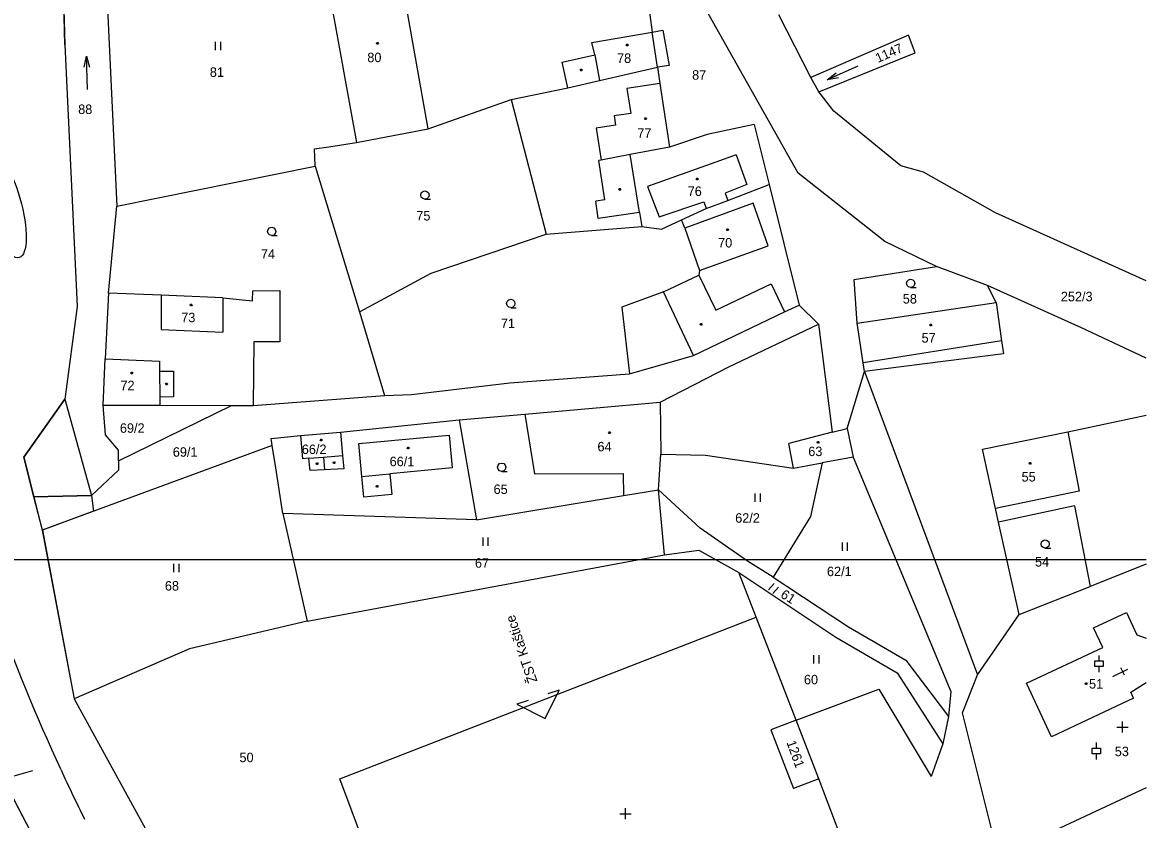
# Model space of a CAD drawing. Extents: x -812394 to -807601, y -1013097 to -1009266.
# Drawn here: x -809827.1 to -809625.5, y -1011046.5 to -1010903.7 of the extents above; entities that cross this region are included whole.
import ezdxf

# ---------------------------------------------------------------- set-up
doc = ezdxf.new("R2010")
doc.units = 0
for name, color, linetype in [('Default', 7, 'Continuous'), ('dočasné zábory', 7, 'Continuous'), ('KLADY_ZMVM', 7, 'Continuous'), ('KN_HRANICE', 7, 'Continuous'), ('KN_KULTURY', 7, 'Continuous'), ('KN_PARCELY', 7, 'Continuous'), ('KN_SLUCKY', 7, 'Continuous'), ('obvod_stavby', 7, 'Continuous'), ('SO02 - Železniční svršek', 7, 'Continuous'), ('SO_Bubliny', 7, 'Continuous')]:
    doc.layers.add(name, color=color, linetype=linetype)

# ---------------------------------------------------------------- blocks, each defined once
blk = doc.blocks.new('304')
at = {"layer": 'Default'}
blk.add_lwpolyline([(0, 0), (-0.38, 0.1), (-0.65, 0.37), (-0.75, 0.74), (-0.65, 1.11), (-0.38, 1.38), (-0.01, 1.48), (0.36, 1.38), (0.63, 1.11), (0.73, 0.73), (0.63, 0.35), (0.36, 0.08), (-0.02, -0.02), (0.98, -0.02)], dxfattribs=at)
blk = doc.blocks.new('306')
at = {"layer": 'Default'}
for p, q in [((-0.5, 1.5), (-0.5, 0)), ((0.5, 0), (0.5, 1.5))]:
    blk.add_line(p, q, dxfattribs=at)
blk = doc.blocks.new('315')
at = {"layer": 'Default'}
for p, q in [((-1, 1), (1, 1)), ((0, 0), (0, 2))]:
    blk.add_line(p, q, dxfattribs=at)
blk = doc.blocks.new('NAHRADNI_SYMBOL')
at = {"layer": 'Default'}
blk.add_lwpolyline([(0.09, 0.15), (0.18, 0), (0.09, -0.15), (-0.09, -0.15), (-0.18, 0), (-0.09, 0.15), (0.09, 0.15)], dxfattribs=at)
blk = doc.blocks.new('802')
at = {"layer": 'Default'}
blk.add_line((-3, 0), (3, 0), dxfattribs=at)
blk.add_lwpolyline([(1, 0.5), (3, 0), (1, -0.5)], dxfattribs=at)
blk = doc.blocks.new('318')
at = {"layer": 'Default'}
blk.add_line((0, 2), (0, 3), dxfattribs=at)
blk.add_lwpolyline([(0, 0), (0, 1), (-0.75, 1), (-0.75, 2), (0, 2), (0.75, 2), (0.75, 1), (0, 1)], dxfattribs=at)
blk = doc.blocks.new('402')
at = {"layer": 'Default'}
blk.add_lwpolyline([(0.09, 0.15), (0.18, 0), (0.09, -0.15), (-0.09, -0.15), (-0.18, 0), (-0.09, 0.15), (0.09, 0.15)], dxfattribs=at)
blk = doc.blocks.new('4091')
at = {"layer": 'Default'}
for p, q in [((0, 0), (0, 3)), ((0.75, 2), (-0.75, 2))]:
    blk.add_line(p, q, dxfattribs=at)

msp = doc.modelspace()

# ---------------------------------------------------------------- linework, layer by layer
at = {"layer": 'Default'}
msp.add_lwpolyline([(-809736.51, -1011025.2), (-809738.53, -1011025.87), (-809733.47, -1011028.41), (-809730.93, -1011023.35), (-809732.95, -1011024.02)], dxfattribs=at)
at = {"layer": 'dočasné zábory'}
msp.add_lwpolyline([(-809825.08, -1010988.69), (-809826.87, -1010981.55), (-809819.55, -1010971.16), (-809814.76, -1010988.43)], close=True, dxfattribs=at)
msp.add_lwpolyline([(-809823.56, -1010994.65), (-809825.08, -1010988.69), (-809814.76, -1010988.43), (-809814.4, -1010991.28), (-809823.56, -1010994.65)], dxfattribs=at)
at = {"layer": 'KLADY_ZMVM'}
msp.add_lwpolyline([(-809625.71, -1011000), (-810000, -1011000), (-810000, -1011500), (-809375, -1011500), (-809375, -1011000)], dxfattribs=at)
at = {"layer": 'KN_HRANICE'}
for p, q in [((-809820.27, -1010877.38), (-809819.54, -1010907.65)), ((-809754.39, -1010922.74), (-809759.51, -1010893.83)), ((-809772.62, -1010895.72), (-809767.28, -1010925.14)), ((-809715.33, -1010897.38), (-809714.24, -1010905.37)), ((-809688.11, -1010930.67), (-809707.45, -1010896.24)), ((-809811.97, -1010899.94), (-809810.23, -1010936.6)), ((-809685.82, -1010913.52), (-809691.58, -1010902.27)), ((-809725.07, -1010907.24), (-809714.24, -1010905.37)), ((-809714.24, -1010905.37), (-809712.36, -1010905.04)), ((-809712.36, -1010905.04), (-809711.25, -1010911.34)), ((-809819.54, -1010907.65), (-809817.34, -1010954.54)), ((-809724.57, -1010909.43), (-809725.07, -1010907.24)), ((-809730.42, -1010910.76), (-809724.57, -1010909.43)), ((-809729.38, -1010915.34), (-809730.42, -1010910.76)), ((-809723.69, -1010914.05), (-809713.3, -1010911.69)), ((-809711.25, -1010911.34), (-809713.3, -1010911.69)), ((-809713.3, -1010911.69), (-809712.87, -1010914.61)), ((-809684.42, -1010916.06), (-809685.82, -1010913.52)), ((-809739.53, -1010917.47), (-809729.38, -1010915.34)), ((-809729.38, -1010915.34), (-809723.69, -1010914.05)), ((-809712.87, -1010914.61), (-809711.14, -1010925.98)), ((-809754.39, -1010922.74), (-809739.53, -1010917.47)), ((-809739.53, -1010917.47), (-809733.26, -1010941.62)), ((-809681.71, -1010919.57), (-809684.42, -1010916.06)), ((-809669.73, -1010929.35), (-809681.71, -1010919.57)), ((-809767.28, -1010925.14), (-809754.39, -1010922.74)), ((-809704.43, -1010923.75), (-809711.14, -1010925.98)), ((-809695.97, -1010921.93), (-809704.43, -1010923.75)), ((-809695.97, -1010921.93), (-809693.3, -1010932.7)), ((-809772.22, -1010925.97), (-809767.28, -1010925.14)), ((-809774.81, -1010926.31), (-809772.22, -1010925.97)), ((-809774.68, -1010929.4), (-809774.81, -1010926.31)), ((-809711.14, -1010925.98), (-809718.2, -1010927.32)), ((-809716.52, -1010937.73), (-809718.2, -1010927.32)), ((-809810.23, -1010936.6), (-809774.68, -1010929.4)), ((-809774.68, -1010929.4), (-809766.75, -1010955.54)), ((-809665.64, -1010930.47), (-809669.73, -1010929.35)), ((-809672.58, -1010942.91), (-809688.11, -1010930.67)), ((-809652.76, -1010937.76), (-809665.64, -1010930.47)), ((-809700.73, -1010935.54), (-809693.3, -1010932.7)), ((-809693.3, -1010932.7), (-809687.95, -1010954.31)), ((-809704.57, -1010937), (-809700.73, -1010935.54)), ((-809811.73, -1010952.15), (-809810.23, -1010936.6)), ((-809716.52, -1010937.73), (-809716.12, -1010940.23)), ((-809708.99, -1010939.05), (-809704.57, -1010937)), ((-809625.71, -1010949.98), (-809652.76, -1010937.76)), ((-809712.62, -1010940.73), (-809708.99, -1010939.05)), ((-809708.43, -1010940.5), (-809708.99, -1010939.05)), ((-809753.89, -1010948.61), (-809733.26, -1010941.62)), ((-809733.26, -1010941.62), (-809716.12, -1010940.23)), ((-809716.12, -1010940.23), (-809712.62, -1010940.73)), ((-809708.43, -1010940.5), (-809705.79, -1010948.11)), ((-809663.31, -1010947.39), (-809672.58, -1010942.91)), ((-809678.08, -1010949.7), (-809663.31, -1010947.39)), ((-809654.15, -1010950.78), (-809663.31, -1010947.39)), ((-809766.75, -1010955.54), (-809753.89, -1010948.61)), ((-809712.21, -1010951.96), (-809705.9, -1010948.93)), ((-809705.79, -1010948.11), (-809705.9, -1010948.93)), ((-809677.51, -1010957.55), (-809678.08, -1010949.7)), ((-809785.87, -1010953.57), (-809785.81, -1010951.78)), ((-809785.81, -1010951.78), (-809780.99, -1010951.72)), ((-809780.99, -1010951.72), (-809780.99, -1010960.93)), ((-809712.21, -1010951.96), (-809719.69, -1010954.69)), ((-809637.34, -1010958.4), (-809654.15, -1010950.78)), ((-809652.62, -1010953.83), (-809654.15, -1010950.78)), ((-809811.73, -1010952.15), (-809812.29, -1010963.93)), ((-809802.28, -1010952.55), (-809811.73, -1010952.15)), ((-809791.19, -1010953.02), (-809802.28, -1010952.55)), ((-809802.28, -1010952.55), (-809802.28, -1010958.7)), ((-809791.19, -1010953.02), (-809785.87, -1010953.57)), ((-809791.19, -1010953.02), (-809791.19, -1010959.17)), ((-809677.51, -1010957.55), (-809652.62, -1010953.83)), ((-809652.62, -1010953.83), (-809651.63, -1010960.74)), ((-809817.34, -1010954.54), (-809819.55, -1010971.19)), ((-809766.75, -1010955.54), (-809762.22, -1010970.5)), ((-809719.69, -1010954.69), (-809718.32, -1010966.65)), ((-809706.83, -1010963.33), (-809690.53, -1010955.54)), ((-809690.53, -1010955.54), (-809687.95, -1010954.31)), ((-809687.95, -1010954.31), (-809684.45, -1010957.75)), ((-809700.5, -1010965.4), (-809684.45, -1010957.75)), ((-809684.45, -1010957.75), (-809682.01, -1010977.11)), ((-809676.47, -1010964.65), (-809677.51, -1010957.55)), ((-809802.28, -1010958.7), (-809791.19, -1010959.17)), ((-809625.71, -1010963.85), (-809637.34, -1010958.4)), ((-809785.63, -1010960.93), (-809785.75, -1010972.3)), ((-809780.99, -1010960.93), (-809785.63, -1010960.93)), ((-809651.63, -1010960.74), (-809651.3, -1010963.06)), ((-809812.69, -1010972.27), (-809812.29, -1010963.93)), ((-809718.32, -1010966.65), (-809706.83, -1010963.33)), ((-809651.3, -1010963.06), (-809676.23, -1010966.23)), ((-809712.82, -1010971.72), (-809700.5, -1010965.4)), ((-809676.23, -1010966.23), (-809676.47, -1010964.65)), ((-809739.76, -1010968.28), (-809718.32, -1010966.65)), ((-809679.34, -1010976.42), (-809676.23, -1010966.23)), ((-809676.23, -1010966.23), (-809655.96, -1011020.63)), ((-809757.42, -1010970.37), (-809739.76, -1010968.28)), ((-809819.55, -1010971.19), (-809826.87, -1010981.55)), ((-809785.75, -1010972.3), (-809762.22, -1010970.5)), ((-809762.22, -1010970.5), (-809757.42, -1010970.37)), ((-809737.1, -1010973.85), (-809712.82, -1010971.72)), ((-809712.82, -1010971.72), (-809712.69, -1010981.07)), ((-809812.22, -1010977.58), (-809812.69, -1010972.27)), ((-809812.69, -1010972.27), (-809802.49, -1010972.27)), ((-809809.94, -1010982.24), (-809789.65, -1010972.3)), ((-809802.49, -1010972.27), (-809789.65, -1010972.3)), ((-809789.65, -1010972.3), (-809785.75, -1010972.3)), ((-809748.85, -1010974.88), (-809737.1, -1010973.85)), ((-809737.1, -1010973.85), (-809735.37, -1010984.59)), ((-809639.78, -1010977.02), (-809625.71, -1010974.08)), ((-809770.14, -1010977.1), (-809748.85, -1010974.88)), ((-809748.85, -1010974.88), (-809745.78, -1010992.82)), ((-809809.94, -1010980.34), (-809812.22, -1010977.58)), ((-809782.57, -1010978.23), (-809777.31, -1010977.72)), ((-809777.31, -1010977.72), (-809770.14, -1010977.1)), ((-809777.31, -1010977.72), (-809776.92, -1010981.88)), ((-809770.14, -1010977.1), (-809769.76, -1010981.28)), ((-809682.01, -1010977.11), (-809679.34, -1010976.42)), ((-809679.34, -1010976.42), (-809678.26, -1010981.58)), ((-809655.06, -1010980.16), (-809639.78, -1010977.02)), ((-809782.36, -1010979.51), (-809823.59, -1010994.66)), ((-809782.36, -1010979.51), (-809782.57, -1010978.23)), ((-809781.71, -1010983.51), (-809782.36, -1010979.51)), ((-809652.76, -1010990.81), (-809655.06, -1010980.16)), ((-809826.87, -1010981.55), (-809825.08, -1010988.69)), ((-809809.94, -1010982.24), (-809809.94, -1010980.34)), ((-809809.94, -1010982.24), (-809809.94, -1010983.94)), ((-809775.78, -1010981.78), (-809776.92, -1010981.88)), ((-809775.61, -1010983.58), (-809775.78, -1010981.78)), ((-809769.76, -1010981.28), (-809769.54, -1010983.67)), ((-809713.13, -1010987.41), (-809712.69, -1010981.07)), ((-809712.69, -1010981.07), (-809704.69, -1010981.22)), ((-809704.69, -1010981.22), (-809688.94, -1010983.58)), ((-809678.26, -1010981.58), (-809683.77, -1010982.61)), ((-809678.26, -1010981.58), (-809660.72, -1011023.58)), ((-809809.94, -1010983.94), (-809814.76, -1010988.43)), ((-809780.48, -1010991.7), (-809781.71, -1010983.51)), ((-809775.59, -1010983.98), (-809775.61, -1010983.58)), ((-809772.99, -1010983.85), (-809775.59, -1010983.98)), ((-809769.54, -1010983.67), (-809772.99, -1010983.85)), ((-809688.94, -1010983.58), (-809683.77, -1010982.61)), ((-809683.77, -1010982.61), (-809685.91, -1010992.23)), ((-809735.37, -1010984.59), (-809719.45, -1010984.53)), ((-809719.45, -1010984.53), (-809719.41, -1010988.45)), ((-809719.41, -1010988.45), (-809713.13, -1010987.41)), ((-809712.03, -1010999.08), (-809713.13, -1010987.41)), ((-809705.68, -1010994.29), (-809713.13, -1010987.41)), ((-809814.76, -1010988.43), (-809825.08, -1010988.69)), ((-809825.08, -1010988.69), (-809823.59, -1010994.66)), ((-809745.78, -1010992.82), (-809719.41, -1010988.45)), ((-809638.59, -1010990.28), (-809652.21, -1010993.26)), ((-809638.59, -1010990.28), (-809635.78, -1011004.74)), ((-809780.48, -1010991.7), (-809776.12, -1011010.98)), ((-809745.78, -1010992.82), (-809780.48, -1010991.7)), ((-809685.91, -1010992.23), (-809692.6, -1011003.11)), ((-809652.21, -1010993.26), (-809652.76, -1010990.81)), ((-809697.2, -1011000.25), (-809705.68, -1010994.29)), ((-809648.52, -1011009.77), (-809652.21, -1010993.26)), ((-809823.59, -1010994.66), (-809817.83, -1011024.91)), ((-809712.03, -1010999.08), (-809705.9, -1010998.23)), ((-809705.9, -1010998.23), (-809698.74, -1011002.28)), ((-809776.12, -1011010.98), (-809712.03, -1010999.08)), ((-809692.6, -1011003.11), (-809697.2, -1011000.25)), ((-809695.65, -1011010.24), (-809698.74, -1011002.28)), ((-809698.74, -1011002.28), (-809681.36, -1011013.87)), ((-809625.71, -1011000.77), (-809635.78, -1011004.74)), ((-809692.6, -1011003.11), (-809679.1, -1011011.97)), ((-809648.52, -1011009.77), (-809635.78, -1011004.74)), ((-809770.25, -1011039.27), (-809695.65, -1011010.24)), ((-809688.47, -1011028.73), (-809695.65, -1011010.24)), ((-809655.96, -1011020.63), (-809648.52, -1011009.77)), ((-809635.16, -1011012.17), (-809629.28, -1011009.42)), ((-809629.28, -1011009.42), (-809627.41, -1011013.42)), ((-809776.12, -1011010.98), (-809797.21, -1011015.92)), ((-809679.1, -1011011.97), (-809668.78, -1011017.98)), ((-809633.51, -1011015.71), (-809635.16, -1011012.17)), ((-809681.36, -1011013.87), (-809670.36, -1011020.23)), ((-809627.41, -1011013.42), (-809625.71, -1011014)), ((-809797.21, -1011015.92), (-809817.83, -1011024.91)), ((-809647.18, -1011022.1), (-809633.51, -1011015.71)), ((-809668.78, -1011017.98), (-809661.16, -1011028.1)), ((-809670.36, -1011020.23), (-809662.17, -1011032.99)), ((-809658.63, -1011027.44), (-809655.96, -1011020.63)), ((-809642.69, -1011031.69), (-809647.18, -1011022.1)), ((-809628.49, -1011023.72), (-809625.71, -1011022)), ((-809688.47, -1011028.73), (-809673.64, -1011023.19)), ((-809673.64, -1011023.19), (-809664.28, -1011038.85)), ((-809660.72, -1011023.58), (-809661.16, -1011028.1)), ((-809627.98, -1011024.81), (-809628.49, -1011023.72)), ((-809817.83, -1011024.91), (-809805.06, -1011048.21)), ((-809627.98, -1011024.81), (-809642.69, -1011031.69)), ((-809836.26, -1011028.53), (-809810.89, -1011076.81)), ((-809661.16, -1011028.1), (-809662.17, -1011032.99)), ((-809652.22, -1011053.19), (-809658.63, -1011027.44)), ((-809688.47, -1011028.73), (-809692.99, -1011030.49)), ((-809692.99, -1011030.49), (-809688.92, -1011040.98)), ((-809684.4, -1011039.22), (-809688.47, -1011028.73)), ((-809662.17, -1011032.99), (-809664.28, -1011038.85)), ((-809752.49, -1011086.54), (-809770.25, -1011039.27)), ((-809684.4, -1011039.22), (-809688.92, -1011040.98)), ((-809677.42, -1011057.54), (-809684.4, -1011039.22)), ((-809625.71, -1011040.87), (-809652.22, -1011053.19))]:
    msp.add_line(p, q, dxfattribs=at)
msp.add_lwpolyline([(-809684.42, -1010916.06), (-809667.12, -1010909.09), (-809668.31, -1010905.92), (-809685.82, -1010913.52)], dxfattribs=at)
at = {"layer": 'KN_SLUCKY'}
for p, q in [((-809713.3, -1010911.69), (-809714.24, -1010905.37)), ((-809724.57, -1010909.43), (-809723.69, -1010914.05)), ((-809712.87, -1010914.61), (-809718.8, -1010915.51)), ((-809718.8, -1010915.51), (-809718.12, -1010919.96)), ((-809718.12, -1010919.96), (-809721.09, -1010920.41)), ((-809721.09, -1010920.41), (-809720.83, -1010922.09)), ((-809720.83, -1010922.09), (-809724.3, -1010922.62)), ((-809724.3, -1010922.62), (-809723.43, -1010928.32)), ((-809718.2, -1010927.32), (-809723.43, -1010928.32)), ((-809699.21, -1010927.36), (-809702.88, -1010928.67)), ((-809699.21, -1010927.36), (-809697.31, -1010932.7)), ((-809723.43, -1010928.32), (-809723.82, -1010928.4)), ((-809722.74, -1010935.45), (-809723.82, -1010928.4)), ((-809702.88, -1010928.67), (-809715.13, -1010933.03)), ((-809715.13, -1010933.03), (-809713, -1010938.48)), ((-809697.31, -1010932.7), (-809701.21, -1010934.27)), ((-809722.74, -1010935.45), (-809724.36, -1010935.68)), ((-809723.94, -1010938.79), (-809724.36, -1010935.68)), ((-809713, -1010938.48), (-809705.03, -1010935.8)), ((-809705.03, -1010935.8), (-809704.57, -1010937)), ((-809701.21, -1010934.27), (-809700.73, -1010935.54)), ((-809716.52, -1010937.73), (-809723.94, -1010938.79)), ((-809696.16, -1010936.04), (-809708.43, -1010940.5)), ((-809693.48, -1010943.7), (-809696.16, -1010936.04)), ((-809705.79, -1010948.11), (-809693.48, -1010943.7)), ((-809705.9, -1010948.93), (-809702.87, -1010955.24)), ((-809706.83, -1010963.33), (-809712.21, -1010951.96)), ((-809702.87, -1010955.24), (-809692.96, -1010950.48)), ((-809692.96, -1010950.48), (-809690.53, -1010955.54)), ((-809651.63, -1010960.74), (-809676.47, -1010964.65)), ((-809812.29, -1010963.93), (-809802.55, -1010964.39)), ((-809802.55, -1010964.39), (-809802.54, -1010966.18)), ((-809802.54, -1010966.18), (-809800.07, -1010966.17)), ((-809802.54, -1010966.18), (-809802.5, -1010970.8)), ((-809800.07, -1010966.17), (-809800.04, -1010970.79)), ((-809800.04, -1010970.79), (-809802.5, -1010970.8)), ((-809802.5, -1010970.8), (-809802.49, -1010972.27)), ((-809766.85, -1010979.12), (-809750.67, -1010977.62)), ((-809750.67, -1010977.62), (-809750.11, -1010983.48)), ((-809682.01, -1010977.11), (-809689.78, -1010979.12)), ((-809639.78, -1010977.02), (-809637.75, -1010987.67)), ((-809766.28, -1010985.05), (-809766.85, -1010979.12)), ((-809688.94, -1010983.58), (-809689.78, -1010979.12)), ((-809775.78, -1010981.78), (-809773.19, -1010981.57)), ((-809773.19, -1010981.57), (-809769.76, -1010981.28)), ((-809773.19, -1010981.57), (-809772.99, -1010983.85)), ((-809750.11, -1010983.48), (-809761.28, -1010984.55)), ((-809766.28, -1010985.05), (-809761.28, -1010984.55)), ((-809765.93, -1010988.73), (-809766.28, -1010985.05)), ((-809761.28, -1010984.55), (-809760.92, -1010988.26)), ((-809760.92, -1010988.26), (-809765.93, -1010988.73)), ((-809637.75, -1010987.67), (-809652.76, -1010990.81))]:
    msp.add_line(p, q, dxfattribs=at)
at = {"layer": 'obvod_stavby'}
for points in [[(-809819.54, -1010907.68), (-809820.27, -1010877.38), (-809829.44, -1010832), (-809848.49, -1010834.46), (-809851.28, -1010798.84), (-809898.47, -1010814.6), (-809898.21, -1010828.41), (-809894.78, -1010861.65), (-809893.92, -1010865.41), (-809892.39, -1010868.68), (-809890.33, -1010872.36)], [(-809819.54, -1010907.65), (-809819.54, -1010907.65), (-809817.34, -1010954.54), (-809819.55, -1010971.16), (-809814.76, -1010988.43), (-809814.4, -1010991.28), (-809823.56, -1010994.65), (-809817.83, -1011024.91), (-809805.06, -1011048.21), (-809802.44, -1011052.2)], [(-809865.72, -1010986.44), (-809864.77, -1010992.44), (-809859.52, -1010995.97), (-809854.51, -1011000.24), (-809850.32, -1011003.33), (-809836.26, -1011028.53), (-809823.58, -1011052.67), (-809818.58, -1011062.18)]]:
    msp.add_lwpolyline(points, dxfattribs=at)
at = {"layer": 'SO02 - Železniční svršek'}
for start, end in [(195.0021, 204.7941), (204.8126, 206.3264)]:
    msp.add_arc((-809483.92, -1010882.18), 370.5, start, end, dxfattribs=at)
at = {"layer": 'SO_Bubliny'}
msp.add_line((-809825.3, -1011037.79), (-809841.77, -1011042.5), dxfattribs=at)
msp.add_ellipse((-809830.53, -1010936), major_axis=(-2.81, 9.81), ratio=0.300573, dxfattribs=at)

# ---------------------------------------------------------------- block references
at = {"layer": 'KN_KULTURY'}
for name, p in [('306', (-809792.06, -1010908.62)), ('402', (-809763.5, -1010907.41)), ('402', (-809718.74, -1010907.68)), ('402', (-809726.99, -1010912.19)), ('402', (-809715.45, -1010920.92)), ('402', (-809706.19, -1010931.69)), ('304', (-809754.99, -1010935.33)), ('402', (-809720.08, -1010933.54)), ('304', (-809782.45, -1010941.85)), ('402', (-809700.76, -1010940.79)), ('304', (-809667.93, -1010951.15)), ('304', (-809739.6, -1010954.76)), ('402', (-809796.9, -1010954.29)), ('402', (-809705.51, -1010957.74)), ('402', (-809664.34, -1010957.87)), ('402', (-809807.54, -1010966.52)), ('402', (-809801.31, -1010968.47)), ('NAHRADNI_SYMBOL', (-809721.91, -1010977.18)), ('402', (-809773.58, -1010978.48)), ('402', (-809757.99, -1010979.91)), ('402', (-809684.53, -1010978.92)), ('402', (-809774.33, -1010982.77)), ('402', (-809771.29, -1010982.58)), ('304', (-809741.22, -1010984.12)), ('402', (-809646.54, -1010982.66)), ('402', (-809763.57, -1010986.79)), ('306', (-809695.36, -1010989.6)), ('306', (-809744.14, -1010997.47)), ('306', (-809679.74, -1010998.4)), ('304', (-809643.82, -1010997.88)), ('306', (-809799.54, -1011002.22)), ('306', (-809684.86, -1011018.57)), ('318', (-809634.18, -1011020.12)), ('402', (-809636.51, -1011022.21)), ('315', (-809629.96, -1011030.96)), ('318', (-809634.65, -1011035.76)), ('315', (-809719.06, -1011046.5))]:
    msp.add_blockref(name, p, dxfattribs=at)
for name, p, rotation in [('802', (-809815.56, -1010912.67), 91.845135), ('802', (-809680.16, -1010912.72), -155.74054600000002), ('306', (-809693.02, -1011005.67), -42.294903), ('4091', (-809631.72, -1011020.9), -63.43704500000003)]:
    msp.add_blockref(name, p, dxfattribs=dict(at, rotation=rotation))

# ---------------------------------------------------------------- texts
at = {"layer": 'Default'}
msp.add_text('ŽST Kaštice', height=1.75, rotation=109.0342, dxfattribs=at).set_placement((-809734.8, -1011021.75))
at = {"layer": 'KN_PARCELY'}
for s, rotation, p in [('1147', 23.892, (-809673.8, -1010910.92)), ('61', 328.362, (-809691.4, -1011006.63)), ('1261', 289.745, (-809690.22, -1011032.7))]:
    msp.add_text(s, height=1.7, rotation=rotation, dxfattribs=at).set_placement(p)
for s, p in [('80', (-809765.32, -1010910.77)), ('78', (-809720.56, -1010910.9)), ('81', (-809793.54, -1010913.4)), ('87', (-809707.11, -1010913.91)), ('88', (-809817.14, -1010920.06)), ('77', (-809716.93, -1010924.34)), ('76', (-809707.9, -1010934.75)), ('75', (-809756.54, -1010939.15)), ('70', (-809702.45, -1010943.99)), ('74', (-809784.39, -1010946)), ('252/3', (-809641.02, -1010953.63)), ('58', (-809669.35, -1010954.04)), ('73', (-809798.67, -1010957.39)), ('71', (-809741.38, -1010958.44)), ('57', (-809665.98, -1010961.04)), ('72', (-809809.57, -1010969.58)), ('69/2', (-809809.66, -1010977.21)), ('69/1', (-809800.18, -1010981.5)), ('66/2', (-809777.06, -1010981.02)), ('64', (-809724.07, -1010980.54)), ('63', (-809686.29, -1010981.39)), ('66/1', (-809761.32, -1010983.2)), ('55', (-809648.06, -1010985.95)), ('65', (-809742.69, -1010988.18)), ('62/2', (-809699.39, -1010993.33)), ('67', (-809746.03, -1011001.4)), ('54', (-809645.65, -1011001.19)), ('62/1', (-809682.94, -1011002.91)), ('68', (-809801.6, -1011005.5)), ('60', (-809687.07, -1011022.3)), ('51', (-809635.97, -1011023.07)), ('50', (-809788.23, -1011036.26)), ('53', (-809631.35, -1011035.18))]:
    msp.add_text(s, height=1.7, dxfattribs=at).set_placement(p)

doc.saveas('drawing.dxf')
